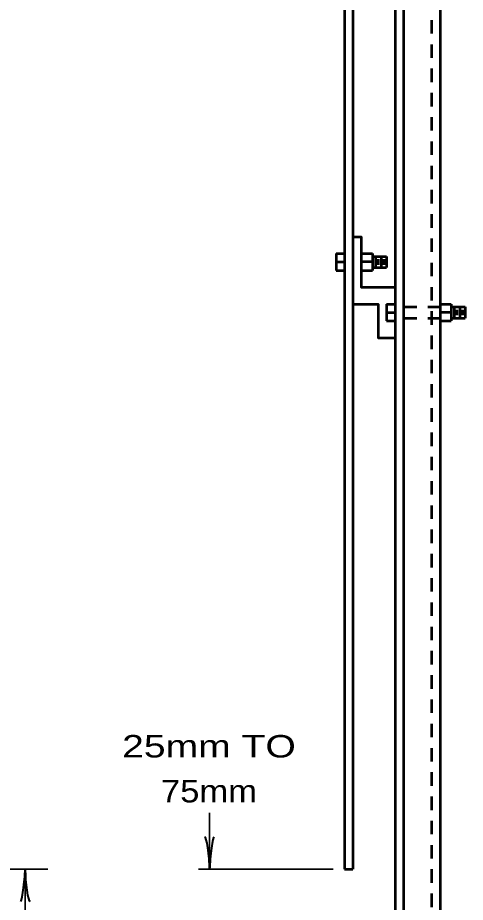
# Model space of a CAD drawing. Extents: x -87 to 768, y -466 to 78.
# Drawn here: x 409.9 to 457.7, y -223 to -128.5 of the extents above; entities that cross this region are included whole.
import ezdxf
from ezdxf.enums import TextEntityAlignment as Align

# ---------------------------------------------------------------- set-up
doc = ezdxf.new("R2010")
doc.units = 0
doc.header["$LTSCALE"] = 0.96
doc.linetypes.add('SHORT_DASHED', pattern=[2.7, 1.5, -1.2])
doc.layers.add('1', color=7, linetype='Continuous', lineweight=53)

msp = doc.modelspace()

# ---------------------------------------------------------------- linework, layer by layer
at = {"layer": '1'}
for p, q in [((444.7887, -35.5407), (444.7887, -219.495)), ((445.6887, -35.5407), (445.6887, -219.495)), ((450.1887, -84.7407), (450.1887, -317.295)), ((451.0887, -84.7407), (451.0887, -317.295)), ((454.9887, -84.7407), (454.9887, -317.295)), ((443.8887, -153.7407), (444.7887, -153.7407)), ((443.8887, -153.7407), (443.8887, -155.5407)), ((446.5887, -153.7407), (447.7887, -153.7407)), ((447.7887, -153.7407), (447.7887, -155.5407)), ((443.8887, -154.6407), (444.7887, -154.6407)), ((447.7887, -154.6407), (446.5887, -154.6407)), ((447.7887, -154.0407), (449.2887, -154.0407)), ((448.0887, -154.0407), (448.0887, -155.2407)), ((448.3887, -154.3407), (448.3887, -154.9407)), ((448.6887, -154.0407), (448.6887, -155.2407)), ((448.9887, -154.3407), (448.9887, -154.9407)), ((449.2887, -154.0407), (449.2887, -155.2407)), ((443.8887, -155.5407), (444.7887, -155.5407)), ((446.5887, -155.5407), (447.7887, -155.5407)), ((447.7887, -155.2407), (449.2887, -155.2407)), ((449.2887, -159.1407), (450.1887, -159.1407)), ((449.2887, -159.1407), (449.2887, -160.9407)), ((454.9887, -159.1407), (456.1887, -159.1407)), ((456.1887, -159.1407), (456.1887, -160.9407)), ((456.1887, -159.4407), (457.6887, -159.4407)), ((456.4887, -159.4407), (456.4887, -160.6407)), ((457.0887, -159.4407), (457.0887, -160.6407)), ((457.6887, -159.4407), (457.6887, -160.6407)), ((449.2887, -160.0407), (450.1887, -160.0407)), ((456.1887, -160.0407), (454.9887, -160.0407)), ((456.1887, -160.6407), (457.6887, -160.6407)), ((456.7887, -159.7407), (456.7887, -160.3407)), ((457.3887, -159.7407), (457.3887, -160.3407)), ((449.2887, -160.9407), (450.1887, -160.9407)), ((454.9887, -160.9407), (456.1887, -160.9407)), ((444.7887, -219.495), (445.6887, -219.495))]:
    msp.add_line(p, q, dxfattribs=at)
at = {"layer": '1', "linetype": 'SHORT_DASHED'}
for p, q in [((454.0887, -84.7407), (454.0887, -317.295)), ((451.0887, -159.4407), (454.9887, -159.4407)), ((451.0887, -160.6407), (454.9887, -160.6407))]:
    msp.add_line(p, q, dxfattribs=at)
at = {"layer": '1', "lineweight": 35}
for p, q in [((430.3887, -213.495), (430.3887, -219.495)), ((322.3887, -219.5093), (413.1002, -219.5093)), ((410.7002, -219.5093), (410.7002, -230.2068)), ((443.5887, -219.495), (429.1887, -219.495))]:
    msp.add_line(p, q, dxfattribs=at)
at = {"layer": '1'}
for points in [[(445.6887, -151.9407), (446.5887, -151.9407), (446.5887, -157.3407), (450.1887, -157.3407)], [(445.6887, -159.1407), (448.3887, -159.1407), (448.3887, -162.7407), (450.1887, -162.7407)]]:
    msp.add_lwpolyline(points, dxfattribs=at)
at = {"layer": '1', "lineweight": 40}
for centre, major_axis, ratio, start_param, end_param in [((430.0571, -218.1856), (0.1874, -2.1428), 0.122415, 0.8963533, 3.1415927), ((430.0571, -218.1856), (0.1874, -2.1428), 0.122415, 0.8963533, 3.1415927), ((430.6426, -218.1504), (-0.2108, -2.1077), 0.07063, 3.1407148, 5.41811), ((430.6426, -218.1504), (-0.2108, -2.1077), 0.07063, 3.1407148, 5.41811), ((410.4463, -220.8539), (0.2108, 2.1077), 0.07063, 3.1407148, 5.41811), ((410.4463, -220.8539), (0.2108, 2.1077), 0.07063, 3.1407148, 5.41811), ((411.0318, -220.8187), (-0.1874, 2.1428), 0.122415, 0.8963533, 3.1415927), ((411.0318, -220.8187), (-0.1874, 2.1428), 0.122415, 0.8963533, 3.1415927)]:
    msp.add_ellipse(centre, major_axis=major_axis, ratio=ratio, start_param=start_param, end_param=end_param, dxfattribs=at)

# ---------------------------------------------------------------- texts
at = {"layer": '1'}
for s, width, p in [('25mm TO', 1.3, (430.3222, -207.5759)), ('75mm', 1.15, (430.3222, -212.3759))]:
    msp.add_text(s, height=2.4, dxfattribs=dict(at, width=width)).set_placement(p, align=Align.CENTER)

doc.saveas('drawing.dxf')
